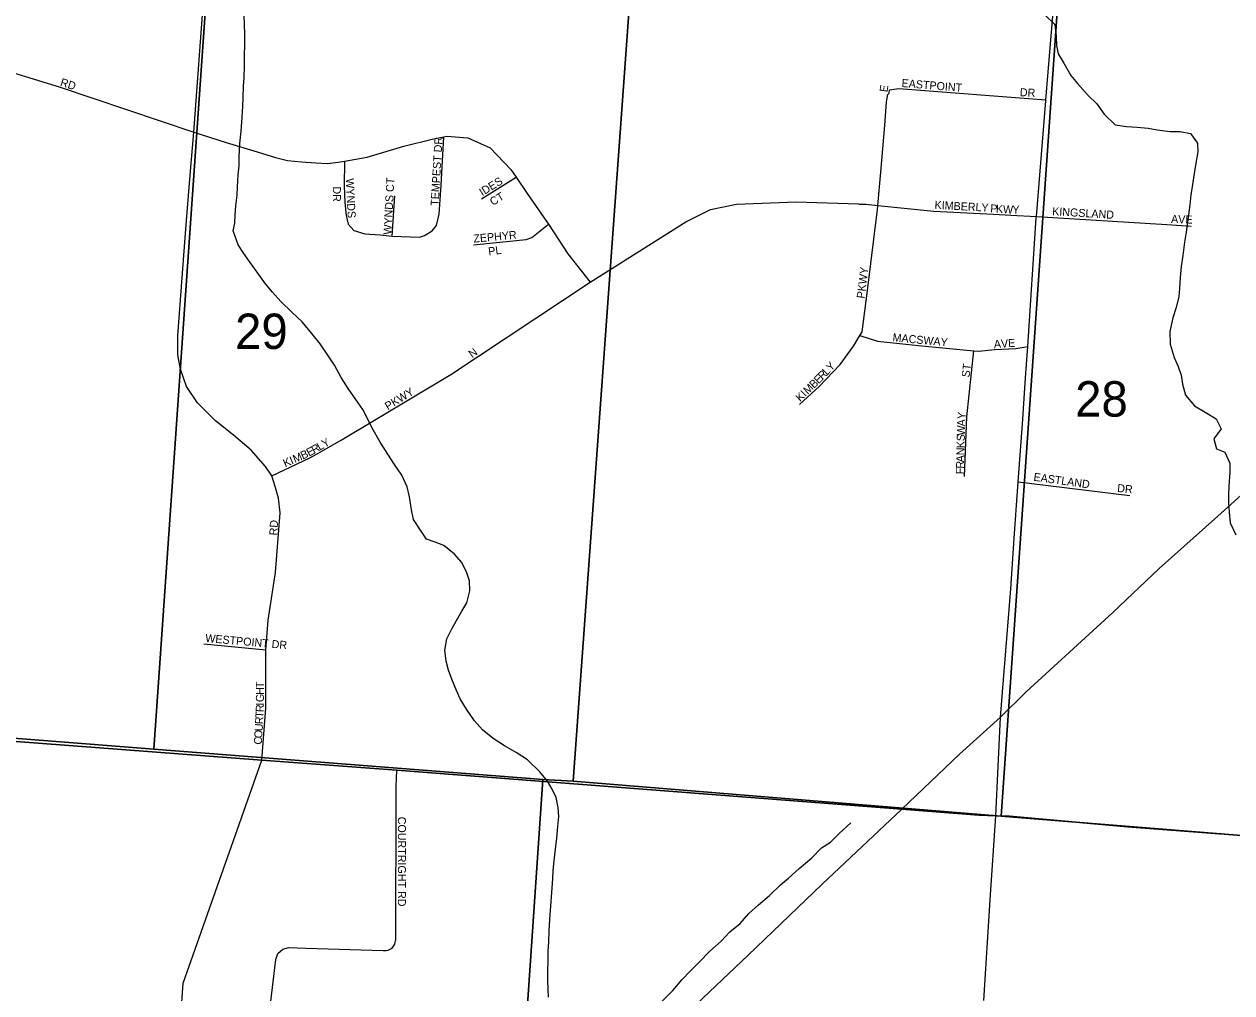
# Model space of a CAD drawing. Extents: x 0 to 34, y 0 to 22.
# Drawn here: x 5.595 to 7.024, y 17.828 to 18.975 of the extents above; entities that cross this region are included whole.
import ezdxf

# ---------------------------------------------------------------- set-up
doc = ezdxf.new("R2010")
doc.units = 0
for name, color, linetype in [('GM_P_County_Alignment', 7, 'Continuous'), ('GM_X_City_Street', 7, 'Continuous'), ('GM_X_City_Street_Text', 7, 'Continuous'), ('GM_X_County_Road', 7, 'Continuous'), ('GM_X_Interstate_Route', 7, 'Continuous'), ('GM_X_Minor_River', 7, 'Continuous'), ('GM_X_Section', 7, 'Continuous'), ('GM_X_Section_Text', 7, 'Continuous'), ('GM_X_State_Route', 7, 'Continuous'), ('GM_X_Township', 7, 'Continuous')]:
    doc.layers.add(name, color=color, linetype=linetype)

msp = doc.modelspace()

# ---------------------------------------------------------------- linework, layer by layer
at = {"layer": 'GM_P_County_Alignment'}
msp.add_lwpolyline([(5.6653, 17.5523), (5.6709, 17.6029), (5.6725, 17.615), (5.6774, 17.6277), (5.6838, 17.6393), (5.6906, 17.6481), (5.7044, 17.6606), (5.7361, 17.6842), (5.7466, 17.6924), (5.7565, 17.7026), (5.763, 17.7119), (5.7672, 17.7192), (5.7706, 17.7271), (5.7733, 17.7359), (5.7752, 17.7436), (5.7767, 17.7516), (5.7807, 17.8057), (5.7833, 17.8401), (5.8763, 18.1039)], dxfattribs=at)
at = {"layer": 'GM_X_City_Street'}
for points in [[(5.7871, 18.7424), (5.7915, 18.7961), (5.7957, 18.8469), (5.8078, 19.0127), (5.8137, 19.0835)], [(4.9958, 19.0197), (5.0049, 19.0151), (5.0292, 19.0127), (5.0652, 19.0092), (5.1641, 19.0039), (5.1767, 19.0025), (5.1982, 19.0001), (5.2536, 18.9938), (5.3044, 18.9898), (5.3396, 18.9798), (5.4571, 18.9517), (5.551, 18.9263), (5.6362, 18.9006), (5.7957, 18.8469)], [(6.5126, 18.5248), (6.5357, 18.546), (6.5605, 18.572), (6.5764, 18.5937), (6.584, 18.6063), (6.5866, 18.6106), (6.5932, 18.6594), (6.605, 18.7552), (6.6054, 18.7601), (6.6089, 18.7995), (6.6134, 18.8548), (6.6155, 18.8829), (6.6172, 18.8912), (6.6187, 18.8931), (6.6192, 18.8969)], [(6.6192, 18.8969), (6.6302, 18.8985), (6.804, 18.8852)], [(5.7957, 18.8469), (5.8339, 18.8346), (5.8706, 18.8235), (5.8926, 18.817), (5.9066, 18.8135), (5.9233, 18.8116), (5.9403, 18.8107), (5.954, 18.8099), (5.9665, 18.8114), (5.974, 18.8127), (6.0007, 18.8174), (6.0443, 18.8301), (6.0793, 18.8391), (6.0916, 18.8414), (6.0952, 18.8421), (6.1199, 18.8401), (6.1463, 18.8282), (6.1709, 18.8027), (6.1772, 18.7934), (6.1901, 18.7742), (6.2135, 18.7407), (6.2154, 18.7378), (6.2383, 18.7027), (6.265, 18.6694)], [(6.0779, 18.7299), (6.0829, 18.7363), (6.0862, 18.7498), (6.0884, 18.7843), (6.0916, 18.8414)], [(5.974, 18.8127), (5.9738, 18.7833), (5.9746, 18.7635), (5.9762, 18.7483), (5.9786, 18.738), (5.9852, 18.7303), (5.998, 18.7266), (6.0161, 18.7255), (6.0305, 18.7237), (6.063, 18.7226), (6.0687, 18.7244), (6.0779, 18.7299)], [(6.1361, 18.7678), (6.1772, 18.7934)], [(6.0305, 18.7237), (6.0337, 18.7714)], [(5.941, 18.4659), (5.9693, 18.482), (6.0998, 18.5602), (6.265, 18.6694), (6.268, 18.6714), (6.3779, 18.7408), (6.4073, 18.7554), (6.438, 18.7616), (6.5088, 18.7644), (6.5822, 18.7619), (6.5836, 18.7618)], [(6.5836, 18.7618), (6.5911, 18.7615), (6.6054, 18.7601), (6.6715, 18.7535)], [(6.6715, 18.7535), (6.7423, 18.7497)], [(5.8763, 18.1039), (5.8809, 18.1652), (5.8808, 18.2343), (5.8836, 18.2696), (5.8924, 18.3258), (5.8979, 18.3965), (5.896, 18.4137), (5.892, 18.4274), (5.8881, 18.4402), (5.8807, 18.4514), (5.8638, 18.4706), (5.8428, 18.4882), (5.8215, 18.5053), (5.8002, 18.5266), (5.7872, 18.5458), (5.7801, 18.5663), (5.7768, 18.5834), (5.7768, 18.6063), (5.7854, 18.7219), (5.7871, 18.7424)], [(6.7423, 18.7497), (6.7423, 18.7497), (6.7626, 18.7487)], [(6.7626, 18.7487), (6.7626, 18.7487), (6.7929, 18.7471)], [(6.7929, 18.7471), (6.9473, 18.7376)], [(6.1267, 18.7137), (6.1892, 18.7197), (6.1957, 18.7222), (6.2154, 18.7378)], [(6.9473, 18.7376), (6.9473, 18.7376), (6.9762, 18.7358)], [(6.584, 18.6063), (6.6049, 18.5996), (6.6535, 18.5944), (6.7189, 18.5882), (6.7245, 18.5877), (6.7438, 18.5895), (6.7684, 18.5909), (6.7826, 18.5931)], [(6.7079, 18.4396), (6.7104, 18.5101), (6.7189, 18.5882)], [(5.8881, 18.4402), (5.9331, 18.4614), (5.941, 18.4659)], [(6.7715, 18.4333), (6.9036, 18.417)], [(5.8076, 18.2413), (5.8808, 18.2343)], [(4.8736, 18.1792), (5.5177, 18.1312), (5.8763, 18.1039), (6.0361, 18.0921), (6.2329, 18.0769)], [(6.0357, 18.0821), (6.0361, 18.0921)], [(6.2329, 18.0769), (6.6267, 18.0466)], [(6.035, 17.9429), (6.0352, 18.0115), (6.0353, 18.0523)], [(6.6267, 18.0466), (6.6338, 18.046), (6.7247, 18.0386), (6.7448, 18.0381)], [(6.7448, 18.0381), (6.7612, 18.0376), (6.8447, 18.0301)], [(6.8447, 18.0301), (6.9008, 18.025), (7.2646, 17.9973)]]:
    msp.add_lwpolyline(points, dxfattribs=at)
at = {"layer": 'GM_X_County_Road'}
for points in [[(6.0354, 18.0622), (6.0354, 18.0733), (6.0357, 18.0821)], [(6.0353, 18.0523), (6.0354, 18.0622)], [(5.8147, 17.4543), (5.8345, 17.4743), (5.8435, 17.4864), (5.8488, 17.5055), (5.8535, 17.5445), (5.8659, 17.6463), (5.8781, 17.7446), (5.8838, 17.7918), (5.8929, 17.8681), (5.8953, 17.8752), (5.9009, 17.8803), (5.9082, 17.8821), (5.9288, 17.8815), (6.02, 17.8785), (6.0235, 17.8787), (6.0256, 17.8788), (6.0305, 17.8815), (6.0338, 17.8861), (6.0347, 17.8916), (6.0349, 17.8976), (6.035, 17.9429)]]:
    msp.add_lwpolyline(points, dxfattribs=at)
at = {"layer": 'GM_X_Interstate_Route'}
for points in [[(7.6785, 18.889), (7.5789, 18.8195), (7.5067, 18.769), (7.1647, 18.5231), (7.0432, 18.4244), (7.0075, 18.3925), (6.9382, 18.3304), (6.8835, 18.2785), (6.7808, 18.1846), (6.7503, 18.1547)], [(6.7503, 18.1547), (6.702, 18.1107), (6.6338, 18.046)], [(6.6338, 18.046), (6.5392, 17.957), (6.4517, 17.8729), (6.3828, 17.8077), (6.3064, 17.727), (6.2509, 17.6728), (6.2053, 17.6234), (6.1901, 17.6054)]]:
    msp.add_lwpolyline(points, dxfattribs=at)
at = {"layer": 'GM_X_Minor_River'}
for points in [[(5.8503, 18.8334), (5.8516, 18.8482), (5.8524, 18.8585), (5.8537, 18.877), (5.8542, 18.888), (5.8547, 18.9013), (5.8552, 18.9116), (5.8557, 18.9249), (5.856, 18.9628), (5.8558, 18.9738), (5.8555, 18.9852)], [(6.804, 18.9843), (6.8149, 18.9743), (6.8162, 18.9603), (6.8169, 18.9493), (6.8187, 18.9394), (6.8254, 18.9283), (6.8336, 18.9138), (6.8415, 18.9043), (6.8542, 18.8901), (6.8643, 18.8802), (6.8733, 18.868), (6.886, 18.8557), (6.8997, 18.8537), (6.9121, 18.8528), (6.9254, 18.8516), (6.936, 18.8496), (6.9511, 18.8476), (6.9632, 18.8475)], [(6.9632, 18.8475), (6.9753, 18.8451), (6.9835, 18.834), (6.9838, 18.8234), (6.9814, 18.8079), (6.9798, 18.798), (6.9778, 18.7851), (6.9758, 18.7726), (6.9745, 18.7609), (6.9721, 18.743), (6.97, 18.7286), (6.9684, 18.7165), (6.9664, 18.701), (6.9643, 18.6877), (6.9631, 18.6748), (6.9622, 18.6619), (6.9614, 18.6524), (6.9582, 18.6392), (6.9543, 18.6271), (6.9507, 18.6111), (6.9514, 18.596), (6.9561, 18.5804), (6.9609, 18.5697), (6.9643, 18.5594), (6.966, 18.5488), (6.9693, 18.5358), (6.9802, 18.5232), (6.9926, 18.5155), (7.0058, 18.5078), (7.0117, 18.4957), (7.0029, 18.484), (7.0062, 18.4722), (7.016, 18.4683), (7.022, 18.455), (7.0219, 18.4443), (7.0206, 18.4284), (7.0201, 18.4178), (7.0204, 18.4083), (7.021, 18.3973), (7.0224, 18.3847), (7.0291, 18.3703)], [(6.2155, 17.8232), (6.2152, 17.8327), (6.2149, 17.8426), (6.2153, 17.8783), (6.2158, 17.8885), (6.2163, 17.9018), (6.2171, 17.9154), (6.218, 17.9261), (6.2198, 17.9526), (6.2206, 17.9632), (6.2211, 17.9731), (6.2224, 17.9848), (6.2236, 17.9985), (6.2253, 18.0114), (6.2265, 18.0254), (6.2278, 18.0372), (6.2271, 18.0474), (6.2246, 18.0596), (6.2198, 18.0695), (6.2145, 18.079), (6.2052, 18.0901), (6.1905, 18.1043), (6.1774, 18.1127), (6.1634, 18.1208), (6.1499, 18.1293), (6.1375, 18.1396), (6.1278, 18.1503), (6.1184, 18.164), (6.111, 18.1762), (6.1065, 18.1861), (6.101, 18.1995), (6.0973, 18.2101), (6.0943, 18.2208), (6.093, 18.2341), (6.095, 18.2473), (6.1011, 18.2591), (6.1065, 18.2689), (6.1131, 18.2802), (6.1189, 18.29), (6.1224, 18.304), (6.1221, 18.3158), (6.1188, 18.3253), (6.1129, 18.3375), (6.1043, 18.3475), (6.0915, 18.3578), (6.0813, 18.3617), (6.0711, 18.3652), (6.064, 18.3759), (6.0558, 18.3885), (6.0533, 18.3999), (6.0508, 18.4154), (6.0482, 18.4272), (6.0419, 18.4409), (6.0326, 18.4547), (6.0225, 18.4703), (6.0162, 18.4799), (6.0065, 18.4974), (6.0013, 18.5081), (5.9957, 18.5187), (5.9875, 18.5306), (5.9785, 18.5435), (5.9703, 18.5565), (5.9621, 18.571), (5.955, 18.5817), (5.9453, 18.5962), (5.9356, 18.6088), (5.924, 18.6226), (5.9116, 18.6337), (5.8989, 18.6463), (5.8887, 18.6574), (5.8805, 18.6673), (5.8727, 18.6784), (5.8626, 18.6925), (5.8551, 18.7032), (5.8484, 18.7135), (5.8425, 18.7299), (5.8441, 18.7393), (5.8446, 18.7492), (5.8454, 18.7598), (5.847, 18.7723), (5.8475, 18.7822), (5.8484, 18.7962), (5.8493, 18.8069), (5.8494, 18.8171), (5.8503, 18.8334)], [(6.3495, 17.8184), (6.3625, 17.8311), (6.3732, 17.844), (6.3835, 17.8545), (6.3939, 17.8647), (6.4065, 17.8778), (6.4198, 17.8895), (6.4302, 17.9008), (6.4424, 17.9106), (6.4527, 17.9222), (6.4642, 17.9328), (6.4772, 17.9437), (6.4902, 17.9561), (6.4997, 17.964), (6.5123, 17.9756), (6.5272, 17.9884), (6.5387, 18.0001), (6.5493, 18.0068), (6.5596, 18.017), (6.5734, 18.0298)]]:
    msp.add_lwpolyline(points, dxfattribs=at)
at = {"layer": 'GM_X_Section'}
for points in [[(5.819, 19.1295), (5.7484, 18.1169), (5.2507, 18.1559), (5.3184, 19.1674)], [(6.3181, 19.0917), (6.2447, 18.0791), (6.2087, 18.0808), (5.7484, 18.1169), (5.819, 19.1295)], [(6.3181, 19.0917), (6.8218, 19.0519), (6.7511, 18.0375), (6.2447, 18.0791)], [(6.8218, 19.0519), (7.324, 19.0124), (7.2561, 17.997), (6.7511, 18.0375)], [(5.1885, 18.1592), (5.2507, 18.1559), (5.7484, 18.1169), (6.2087, 18.0808), (6.1439, 17.131), (5.123, 17.2087)], [(6.2087, 18.0808), (6.2447, 18.0791), (6.7511, 18.0375), (7.2561, 17.997), (7.1918, 17.0445), (6.1439, 17.131)]]:
    msp.add_lwpolyline(points, close=True, dxfattribs=at)
at = {"layer": 'GM_X_State_Route'}
for points in [[(6.7801, 18.5561), (6.7826, 18.5931), (6.7928, 18.7456), (6.7929, 18.7471), (6.8039, 18.8839), (6.804, 18.8852), (6.8177, 19.0455)], [(6.7767, 18.5071), (6.7789, 18.5381), (6.78, 18.5558), (6.7801, 18.5561)], [(6.7663, 18.3602), (6.7664, 18.3604), (6.7715, 18.4333), (6.7767, 18.5068), (6.7767, 18.5071)], [(6.7598, 18.2721), (6.7598, 18.2723), (6.7626, 18.3067), (6.7663, 18.3602)], [(6.7527, 18.184), (6.7527, 18.1841), (6.7598, 18.2721)], [(6.7448, 18.0381), (6.7503, 18.1547), (6.7527, 18.184)], [(6.7383, 17.9387), (6.7448, 18.0381)], [(6.7306, 17.8193), (6.7383, 17.9387)]]:
    msp.add_lwpolyline(points, dxfattribs=at)
at = {"layer": 'GM_X_Township'}
for points in [[(5.5177, 18.1312), (5.8763, 18.1039), (6.0361, 18.0921), (6.6338, 18.046), (6.7247, 18.0386), (6.7448, 18.0381), (6.7612, 18.0376), (6.9008, 18.025), (7.3953, 17.9873), (7.4612, 17.9831), (7.4838, 17.9835), (7.5026, 17.9842), (7.5797, 17.9729), (7.6687, 17.9677), (7.9634, 17.9394), (7.994, 17.9365), (8.1574, 17.9293), (8.2509, 17.9206), (8.2846, 17.9178), (8.6396, 17.8902), (9.2909, 17.8381), (9.3736, 17.8315), (9.4, 17.8295)], [(9.4, 17.8295), (9.3736, 17.8315), (9.2909, 17.8381), (8.6396, 17.8902), (8.2846, 17.9178), (8.2509, 17.9206), (8.1574, 17.9293), (7.994, 17.9365), (7.9634, 17.9394), (7.6687, 17.9677), (7.5797, 17.9729), (7.5026, 17.9842), (7.4838, 17.9835), (7.4612, 17.9831), (7.3953, 17.9873), (6.9008, 18.025), (6.7612, 18.0376), (6.7448, 18.0381), (6.7247, 18.0386), (6.6338, 18.046), (6.0361, 18.0921), (5.8763, 18.1039), (5.5177, 18.1312)]]:
    msp.add_lwpolyline(points, dxfattribs=at)

# ---------------------------------------------------------------- texts
at = {"layer": 'GM_X_City_Street_Text'}
for s, rotation, p in [('RD', 342.4739, (5.6369, 18.9019)), ('EASTPOINT', 355.4856, (6.6331, 18.9003)), ('E', 81.6154, (6.6166, 18.8937)), ('DR', 356.989, (6.7731, 18.8895)), ('TEMPEST DR', 86.6328, (6.0854, 18.7595)), ('DR', 270, (5.9603, 18.7827)), ('WYNDS', 272.8804, (5.9756, 18.792)), ('WYNDS CT', 86.8218, (6.0295, 18.7253)), ('IDES', 31.6047, (6.1371, 18.7709)), ('CT', 30.9616, (6.1496, 18.7595)), ('KIMBERLY', 356.8625, (6.6722, 18.7562)), ('P', 356.0896, (6.7381, 18.752)), ('K', 356.1114, (6.7448, 18.7516)), ('W', 356.9475, (6.7532, 18.751)), ('Y', 359.7296, (6.7645, 18.7504)), ('KINGSLAND', 356.467, (6.8114, 18.7487)), ('AVE', 358.0261, (6.9522, 18.7395)), ('ZEPHYR', 5.2911, (6.127, 18.7161)), ('PL', 7.1217, (6.1448, 18.701)), ('PKWY', 82.8736, (6.5895, 18.6496)), ('MACSWAY', 354.5939, (6.6224, 18.5995)), ('AVE', 3.9506, (6.7429, 18.5912)), ('N', 36.8743, (6.1252, 18.5792)), ('L', 46.0366, (6.5451, 18.5586)), ('Y', 46.0466, (6.5498, 18.5634)), ('ST', 82.8783, (6.7137, 18.5563)), ('B', 44.428, (6.5297, 18.543)), ('E', 45.7491, (6.5352, 18.5484)), ('R', 46.0249, (6.5399, 18.5532)), ('PKWY', 31.5359, (6.0254, 18.5176)), ('K', 43.8561, (6.5134, 18.5273)), ('I', 43.8571, (6.5194, 18.5331)), ('M', 43.8408, (6.5224, 18.536)), ('Y', 84.7027, (6.7087, 18.5068)), ('W', 88.5004, (6.7082, 18.4878)), ('A', 88.5065, (6.7085, 18.4986)), ('Y', 29.9351, (5.9504, 18.4732)), ('K', 88.492, (6.7078, 18.4728)), ('S', 88.4969, (6.7081, 18.4811)), ('M', 23.8628, (5.9154, 18.4553)), ('B', 24.5919, (5.9246, 18.4594)), ('E', 28.5926, (5.9321, 18.4628)), ('R', 29.8585, (5.9381, 18.4661)), ('L', 29.9256, (5.9446, 18.4698)), ('N', 88.492, (6.7076, 18.4644)), ('K', 23.8559, (5.9039, 18.4502)), ('I', 23.8471, (5.9116, 18.4536)), ('R', 88.4938, (6.7072, 18.4486)), ('A', 88.5065, (6.7074, 18.4561)), ('F', 88.4969, (6.707, 18.4419)), ('EASTLAND', 352.094, (6.7891, 18.4345)), ('DR', 353.9934, (6.8882, 18.4212)), ('RD', 86.9775, (5.8945, 18.3695)), ('WESTPOINT DR', 354.9086, (5.809, 18.2437)), ('T', 89.9956, (5.8787, 18.1892)), ('G', 89.9703, (5.8787, 18.1725)), ('H', 89.9928, (5.8787, 18.1809)), ('R', 87.9858, (5.8784, 18.1605)), ('I', 89.7461, (5.8787, 18.1683)), ('R', 86.6949, (5.8776, 18.1461)), ('T', 86.7224, (5.878, 18.1536)), ('O', 86.7165, (5.8766, 18.1295)), ('U', 86.7195, (5.8771, 18.1378)), ('C', 86.7191, (5.8762, 18.122)), ('COURTRIGHT RD', 270, (6.0373, 18.0369))]:
    msp.add_text(s, height=0.00947, rotation=rotation, dxfattribs=at).set_placement(p)
at = {"layer": 'GM_X_Section_Text'}
for s, p in [('29', (5.8446, 18.5903)), ('28', (6.8388, 18.5103))]:
    msp.add_text(s, height=0.04186, rotation=0, dxfattribs=at).set_placement(p)

doc.saveas('drawing.dxf')
